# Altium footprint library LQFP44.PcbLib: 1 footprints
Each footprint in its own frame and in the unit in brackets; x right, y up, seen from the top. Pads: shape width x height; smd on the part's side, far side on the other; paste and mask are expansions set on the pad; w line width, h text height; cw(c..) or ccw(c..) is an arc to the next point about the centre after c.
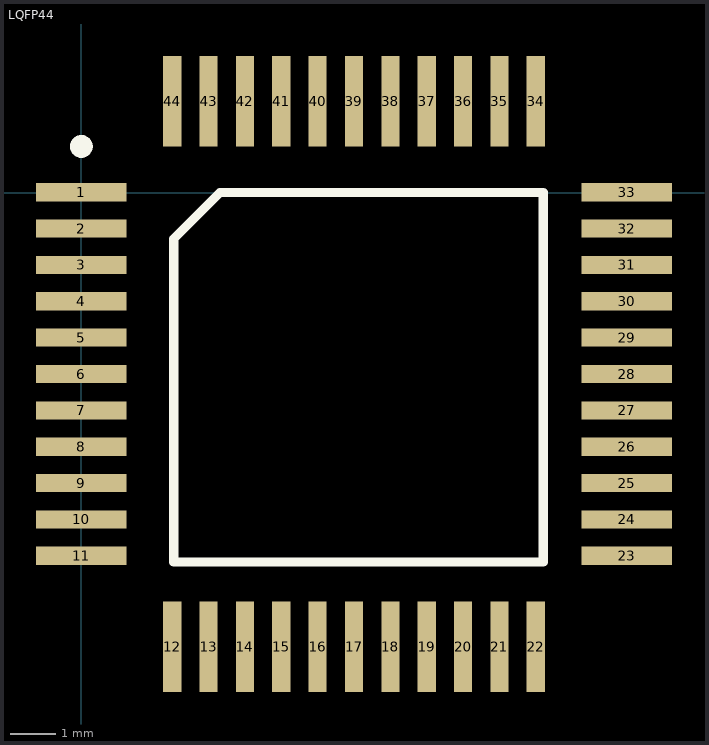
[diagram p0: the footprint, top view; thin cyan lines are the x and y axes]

## LQFP44 [mm]
pads (44):
  rect 2x0.4 smd: 1(-0.003,0.01) 2(-0.003,-0.79) 3(-0.003,-1.59) 4(-0.003,-2.39) 5(-0.003,-3.19) 6(-0.003,-3.99) 7(-0.003,-4.79) 8(-0.003,-5.59) 9(-0.003,-6.39) 10(-0.003,-7.19) 11(-0.003,-7.99) 23(11.997,-7.99) 24(11.997,-7.19) 25(11.997,-6.39) 26(11.997,-5.59) 27(11.997,-4.79) 28(11.997,-3.99) 29(11.997,-3.19) 30(11.997,-2.39) 31(11.997,-1.59) 32(11.997,-0.79) 33(11.997,0.01)
  rect 0.4x2 smd: 12(1.997,-9.99) 13(2.797,-9.99) 14(3.597,-9.99) 15(4.397,-9.99) 16(5.197,-9.99) 17(5.997,-9.99) 18(6.797,-9.99) 19(7.597,-9.99) 20(8.397,-9.99) 21(9.197,-9.99) 22(9.997,-9.99) 34(9.997,2.01) 35(9.197,2.01) 36(8.397,2.01) 37(7.597,2.01) 38(6.797,2.01) 39(5.997,2.01) 40(5.197,2.01) 41(4.397,2.01) 42(3.597,2.01) 43(2.797,2.01) 44(1.997,2.01)
Top Overlay:
  circle w0.25: c0,1.016 r0.125
  lines w0.2: 2.032,-8.128 10.16,-8.128 10.16,0 3.048,0 2.032,-1.016 2.032,-8.128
